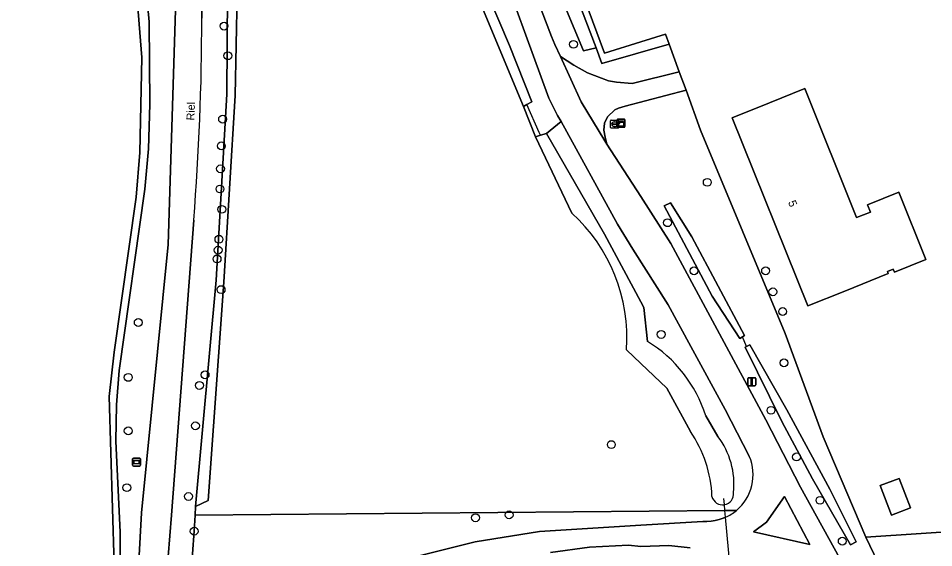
# Model space of a CAD drawing. Extents: x 163859 to 164644, y 379566 to 382155.
# Drawn here: x 164422.2 to 164536.6, y 381338.2 to 381404.3 of the extents above; entities that cross this region are included whole.
import ezdxf

# ---------------------------------------------------------------- set-up
doc = ezdxf.new("R2010")
doc.units = 0
for name, color, linetype in [('IMGEO_Boom', 7, 'Continuous'), ('IMGEO_Duiker', 7, 'Continuous'), ('IMGEO_Erf', 7, 'Continuous'), ('IMGEO_Grasland_agrarisch', 7, 'Continuous'), ('IMGEO_Grasland_overig', 7, 'Continuous'), ('IMGEO_Groenvoorziening', 7, 'Continuous'), ('IMGEO_Informatiebord', 7, 'Continuous'), ('IMGEO_Kast', 7, 'Continuous'), ('IMGEO_Lichtmast', 7, 'Continuous'), ('IMGEO_Openbare_ruimte_label', 7, 'Continuous'), ('IMGEO_Pand', 7, 'Continuous'), ('IMGEO_Pand_nummerreeks', 7, 'Continuous'), ('IMGEO_Rijbaan_lokaal_gesloten', 7, 'Continuous'), ('IMGEO_Rijbaan_lokaal_onverhard', 7, 'Continuous'), ('IMGEO_Rioolput', 7, 'Continuous'), ('IMGEO_Waterloop', 7, 'Continuous')]:
    doc.layers.add(name, color=color, linetype=linetype)

msp = doc.modelspace()

# ---------------------------------------------------------------- linework, layer by layer
at = {"layer": 'IMGEO_Boom'}
for centre in [(164447.92, 381403.31), (164491.58, 381401.04), (164448.4, 381399.61), (164447.74, 381391.69), (164447.58, 381388.35), (164447.48, 381385.49), (164447.41, 381382.97), (164508.3, 381383.8), (164447.64, 381380.42), (164503.34, 381378.75), (164447.28, 381376.69), (164447.18, 381375.33), (164447.05, 381374.23), (164506.65, 381372.74), (164515.59, 381372.75), (164447.55, 381370.4), (164516.5, 381370.12), (164517.72, 381367.66), (164437.2, 381366.29), (164502.54, 381364.8), (164517.89, 381361.25), (164435.95, 381359.43), (164445.55, 381359.75), (164444.85, 381358.43), (164516.26, 381355.32), (164444.35, 381353.39), (164435.95, 381352.75), (164496.32, 381351.04), (164519.46, 381349.5), (164435.78, 381345.66), (164443.48, 381344.56), (164522.39, 381344.08), (164479.34, 381341.9), (164483.54, 381342.26), (164444.19, 381340.22), (164525.17, 381338.97)]:
    msp.add_circle(centre, 0.489, dxfattribs=at)
at = {"layer": 'IMGEO_Duiker'}
for points in [[(164487.45, 381389.67), (164487.29, 381390.03), (164485.77, 381393.51)], [(164513.19, 381363.29), (164512.71, 381364.51)], [(164511.24, 381334.6), (164511.23, 381334.72), (164510.95, 381337.93), (164510.59, 381341.96), (164510.51, 381342.79), (164510.45, 381343.54), (164510.38, 381344.3)]]:
    msp.add_lwpolyline(points, dxfattribs=at)
at = {"layer": 'IMGEO_Erf'}
for points in [[(164565.06, 381406.39), (164564.53, 381407.1), (164559.87, 381421.34), (164557.52, 381431.13), (164500, 381418.46), (164489.46, 381416.14), (164495.45, 381399.95), (164500, 381401.35), (164503.1, 381402.3), (164503.54, 381401.07), (164504.8, 381397.62), (164505.66, 381395.29), (164507.47, 381390.32), (164518.04, 381364.93), (164522.77, 381352.02), (164528.1, 381339.46), (164564.56, 381341.91), (164578.44, 381343.7), (164575.05, 381361.38)], [(164535.63, 381374.14), (164531.69, 381372.56), (164531.54, 381372.95), (164530.81, 381372.66), (164530.92, 381372.39), (164525.51, 381370.22), (164520.86, 381368.36), (164511.43, 381391.87), (164516.07, 381393.74), (164520.5, 381395.51), (164526.97, 381379.39), (164528.68, 381380.07), (164528.32, 381380.98), (164532.25, 381382.56)], [(164533.68, 381343.13), (164531.33, 381342.22), (164529.9, 381345.91), (164532.26, 381346.82)]]:
    msp.add_lwpolyline(points, close=True, dxfattribs=at)
at = {"layer": 'IMGEO_Grasland_agrarisch'}
msp.add_lwpolyline([(164483.06, 381430.48), (164490.42, 381411.1), (164490.61, 381410.59), (164490.75, 381410.23), (164494.4, 381400.61), (164495.14, 381398.66), (164503.54, 381401.07), (164503.1, 381402.3), (164500, 381401.35), (164495.45, 381399.95), (164489.46, 381416.14), (164500, 381418.46), (164557.52, 381431.13), (164557.45, 381431.4), (164557.26, 381432.21), (164549, 381466.6), (164546.85, 381478.96), (164529.2, 381476.95), (164529.29, 381476.74), (164517.19, 381468.15), (164512.46, 381467.01), (164475.43, 381450.48), (164478.57, 381441.47)], dxfattribs=at)
at = {"layer": 'IMGEO_Grasland_overig'}
msp.add_lwpolyline([(164564.61, 381431.54), (164564.53, 381431.95), (164564.32, 381432.7), (164557.45, 381431.4), (164557.52, 381431.13), (164559.87, 381421.34), (164564.53, 381407.1), (164565.06, 381406.39), (164575.05, 381361.38), (164578.44, 381343.7), (164564.56, 381341.91), (164528.1, 381339.46), (164536.3, 381322.47), (164537.45, 381326.82), (164537.92, 381328.61), (164537.74, 381328.6)], dxfattribs=at)
at = {"layer": 'IMGEO_Groenvoorziening'}
for points in [[(164437.62, 381342.51), (164440.93, 381376.03), (164442.03, 381410.67), (164442.31, 381432.69), (164442.26, 381444.54), (164442.24, 381448.35), (164442.22, 381457.68), (164442.22, 381458.62), (164442.05, 381465.53), (164441.98, 381468.27), (164441.6, 381500), (164440.42, 381600.95)], [(164438.34, 381499.7), (164438.46, 381494.53), (164440.25, 381494.63), (164440.8, 381475.11), (164440.95, 381465.52), (164440.98, 381463.45), (164439.18, 381444.59), (164438.14, 381433.63), (164436.48, 381433.86), (164436.26, 381427.88), (164437.58, 381427.9), (164437.21, 381424.46), (164437.16, 381415.96), (164437.47, 381412.38), (164438.23, 381407.47), (164438.58, 381403.85), (164438.66, 381393.57), (164438.49, 381387.99), (164438.01, 381382.93), (164434.81, 381360.28), (164434.48, 381356.02), (164434.38, 381351.46), (164434.92, 381340.08), (164434.91, 381333.02)], [(164445.79, 381457.7), (164445.75, 381455.9), (164445.61, 381444.5), (164445.14, 381404.29)], [(164479.27, 381411.35), (164479.59, 381410.3), (164483.6, 381400.91), (164486.37, 381393.84), (164485.77, 381393.51), (164485.33, 381393.26), (164486.82, 381389.49), (164487.45, 381389.67), (164488.22, 381389.88), (164490.06, 381391.38), (164489.58, 381392.13), (164488.52, 381394.29), (164481.62, 381413.16), (164472.89, 381433.3), (164468.06, 381442.36), (164461.3, 381450.96), (164453.83, 381458.42)], [(164444.13, 381379.08), (164441.34, 381342.21), (164440.75, 381334.49), (164440.65, 381333.45), (164440.79, 381332.88), (164440.97, 381332.32), (164441.21, 381331.78), (164441.49, 381331.26), (164441.81, 381330.78), (164442.18, 381330.32), (164442.58, 381329.9), (164443.03, 381329.51), (164443.5, 381329.17), (164443.79, 381334.56), (164444.19, 381340.22), (164444.31, 381342.24), (164444.37, 381343.32), (164446.95, 381371.56), (164448.25, 381394.83), (164448.45, 381420.11), (164447.94, 381444.47), (164447.88, 381447.15), (164448.54, 381452.5)], [(164449.93, 381450.68), (164449.82, 381420.02), (164449.32, 381394.65), (164447.9, 381371.31), (164445.92, 381344.04), (164444.37, 381343.32), (164444.31, 381342.24), (164510.51, 381342.79), (164511.93, 381342.81)], [(164478.57, 381441.47), (164475.43, 381450.48), (164471, 381448.5), (164469.83, 381445.64), (164475.49, 381433.77), (164484.2, 381414.14), (164488.82, 381402.01), (164489.26, 381401.03), (164489.95, 381399.53), (164491.62, 381398.45), (164493.32, 381397.48), (164495.95, 381396.49), (164496.96, 381396.31), (164498.9, 381396.14), (164504.8, 381397.62), (164503.54, 381401.07), (164495.14, 381398.66), (164494.4, 381400.61), (164492.84, 381400.24), (164481.04, 381428.46)], [(164434.19, 381336.08), (164433.57, 381357.04), (164434.19, 381362.6), (164436.96, 381381.93), (164437.41, 381387.54), (164437.63, 381399.41), (164436.95, 381408.32), (164436.41, 381411.28), (164435.98, 381417.22), (164436.15, 381420.7), (164436.03, 381423.26), (164436.26, 381427.88), (164436.48, 381433.86), (164436.54, 381434.61), (164436.27, 381435.91), (164435.14, 381436.53), (164433.06, 381437.13), (164419.72, 381439.84)], [(164491.37, 381379.95), (164486.82, 381389.49), (164485.33, 381393.26), (164477.93, 381411.1)], [(164536.3, 381322.47), (164528.1, 381339.46), (164522.77, 381352.02), (164518.04, 381364.93), (164507.47, 381390.32), (164505.66, 381395.29), (164498.04, 381393.32), (164497.2, 381393.06), (164496.74, 381392.84), (164495.84, 381391.97), (164495.47, 381391.17), (164495.39, 381390.32), (164495.53, 381389.45), (164495.77, 381388.57), (164500, 381382.04), (164503.75, 381376.16), (164515.61, 381354.14), (164519.97, 381345.71), (164525.51, 381335.7)], [(164513.55, 381349.6), (164510.53, 381355.42), (164506.25, 381363.3), (164503.41, 381368.49), (164499.01, 381375.46), (164497.08, 381378.56), (164490.06, 381391.38), (164488.22, 381389.88), (164495.48, 381377.34), (164500, 381368.88), (164500.39, 381368.15), (164500.84, 381363.93)], [(164506.21, 381352.67), (164503.23, 381358.09), (164500, 381361.18), (164498.22, 381362.87)], [(164508.12, 381354.62), (164509.63, 381352.06)], [(164425.7, 381295.54), (164428.74, 381302.37), (164431.24, 381307.56), (164433.55, 381313.72), (164435.38, 381319.58), (164436.27, 381323.37), (164436.86, 381328.83), (164437.62, 381342.51)], [(164511.93, 381342.81), (164510.51, 381342.79), (164444.31, 381342.24), (164444.19, 381340.22), (164443.79, 381334.56), (164443.5, 381329.17), (164444.01, 381328.87), (164444.54, 381328.61), (164445.09, 381328.41), (164445.65, 381328.25), (164446.23, 381328.15), (164446.81, 381328.1), (164447.4, 381328.1), (164447.99, 381328.15), (164448.56, 381328.25), (164449.13, 381328.41), (164449.43, 381328.52), (164464.88, 381334.66)], [(164464.88, 381334.66), (164471.46, 381336.92), (164479.32, 381338.91), (164487.33, 381340.19), (164500, 381340.97), (164507.73, 381341.45), (164508.25, 381341.43), (164508.78, 381341.47), (164509.29, 381341.54), (164509.8, 381341.67), (164510.3, 381341.84), (164510.59, 381341.96)], [(164506.16, 381338.16), (164503.52, 381338.44), (164500, 381338.33), (164498.45, 381338.47), (164493.57, 381338.22), (164488.73, 381337.54)]]:
    msp.add_lwpolyline(points, dxfattribs=at)
for points in [[(164512.96, 381364.66), (164512.71, 381364.51), (164512.38, 381364.31), (164508.91, 381369.56), (164502.9, 381380.88), (164503.7, 381381.24), (164506.38, 381376.97)], [(164518.23, 381355.39), (164523.62, 381345.49), (164526.91, 381338.9), (164526.21, 381338.53), (164521.46, 381346.77), (164517.64, 381353.91), (164513.02, 381363.21), (164513.19, 381363.29), (164513.62, 381363.49)], [(164521.12, 381338.58), (164517.97, 381344.54), (164515.72, 381341.34), (164514.08, 381340.16)]]:
    msp.add_lwpolyline(points, close=True, dxfattribs=at)
for centre, radius, start, end in [((164127.19, 381404.33), 317.95, 355.4455, 359.9916), ((164477.32, 381364.4), 20.95, 355.8205, 47.8876), ((164491.98, 381349.5), 16.93, 17.6325, 58.4553), ((164493.52, 381343.98), 15.38, 2.1274, 34.4033), ((164501.78, 381346.09), 9.86, 353.957, 37.2698), ((164508.17, 381347.29), 5.86, 310.0111, 23.194), ((164510.22, 381344.89), 1.38, 194.5224, 279.6002), ((164510.22, 381344.9), 1.38, 279.6512, 6.4516), ((164508.16, 381347.3), 5.87, 294.4431, 310.0184)]:
    msp.add_arc(centre, radius, start, end, dxfattribs=at)
at = {"layer": 'IMGEO_Informatiebord'}
for p, q in [((164436.49, 381348.45), (164436.49, 381349.25)), ((164436.49, 381349.25), (164436.49, 381348.45)), ((164436.59, 381349.35), (164437.38, 381349.35)), ((164437.38, 381349.35), (164436.59, 381349.35)), ((164437.48, 381349.25), (164437.48, 381348.45)), ((164437.48, 381348.45), (164437.48, 381349.25)), ((164437.38, 381348.35), (164436.59, 381348.35)), ((164436.59, 381348.35), (164437.38, 381348.35))]:
    msp.add_line(p, q, dxfattribs=at)
for points in [[(164436.6, 381349.08), (164437.38, 381349.08), (164437.38, 381348.62), (164436.6, 381348.62), (164436.6, 381349.08)], [(164436.66, 381349.02), (164436.66, 381348.68), (164437.32, 381348.68), (164437.32, 381349.02), (164436.66, 381349.02)]]:
    msp.add_lwpolyline(points, dxfattribs=at)
for centre, start, end in [((164436.59, 381349.25), 90, 180), ((164436.59, 381349.25), 90, 180), ((164437.38, 381349.25), 0, 90), ((164437.38, 381349.25), 360, 90), ((164436.59, 381348.45), 180, 270), ((164436.59, 381348.45), 180, 270), ((164437.38, 381348.45), 270, 0), ((164437.38, 381348.45), 270, 0)]:
    msp.add_arc(centre, 0.1, start, end, dxfattribs=at)
at = {"layer": 'IMGEO_Kast'}
for p, q in [((164497.02, 381390.76), (164497.02, 381391.6)), ((164497.02, 381391.6), (164497.02, 381390.76)), ((164497.1, 381391.68), (164497.94, 381391.68)), ((164497.94, 381391.68), (164497.1, 381391.68)), ((164498.02, 381391.61), (164498.02, 381390.77)), ((164498.02, 381390.77), (164498.02, 381391.61)), ((164497.95, 381390.68), (164497.11, 381390.68)), ((164497.11, 381390.68), (164497.95, 381390.68))]:
    msp.add_line(p, q, dxfattribs=at)
for points in [[(164497.22, 381391.47), (164497.82, 381391.47), (164497.82, 381391.39), (164497.22, 381391.39), (164497.22, 381391.47)], [(164497.22, 381391.3), (164497.82, 381391.3), (164497.82, 381390.81), (164497.22, 381390.81), (164497.22, 381391.3)]]:
    msp.add_lwpolyline(points, dxfattribs=at)
msp.add_circle((164497.3, 381391.14), 0.0377, dxfattribs=at)
for centre, start, end in [((164497.1, 381391.6), 92.4484, 184.2845), ((164497.1, 381391.6), 92.4484, 184.2845), ((164497.94, 381391.6), 2.4484, 94.2845), ((164497.94, 381391.6), 2.4484, 94.2845), ((164497.1, 381390.76), 182.4484, 274.2845), ((164497.1, 381390.76), 182.4484, 274.2845), ((164497.94, 381390.76), 272.4484, 4.2845), ((164497.94, 381390.76), 272.4484, 4.2845)]:
    msp.add_arc(centre, 0.0779, start, end, dxfattribs=at)
at = {"layer": 'IMGEO_Lichtmast'}
for p, q in [((164513.37, 381358.49), (164513.37, 381359.29)), ((164513.37, 381359.29), (164513.37, 381358.49)), ((164513.47, 381359.39), (164514.25, 381359.39)), ((164514.25, 381359.39), (164513.47, 381359.39)), ((164514.35, 381359.29), (164514.35, 381358.49)), ((164514.35, 381358.49), (164514.35, 381359.29)), ((164514.25, 381358.39), (164513.47, 381358.39)), ((164513.47, 381358.39), (164514.25, 381358.39))]:
    msp.add_line(p, q, dxfattribs=at)
msp.add_lwpolyline([(164513.78, 381359.26), (164513.93, 381359.26), (164513.93, 381358.51), (164513.78, 381358.51), (164513.78, 381359.26)], dxfattribs=at)
for centre, start, end in [((164513.47, 381359.29), 90, 180), ((164513.47, 381359.29), 90, 180), ((164514.25, 381359.29), 0, 90), ((164514.25, 381359.29), 360, 90), ((164513.47, 381358.49), 180, 270), ((164513.47, 381358.49), 180, 270), ((164514.25, 381358.49), 270, 0), ((164514.25, 381358.49), 270, 0)]:
    msp.add_arc(centre, 0.1, start, end, dxfattribs=at)
at = {"layer": 'IMGEO_Pand'}
for points in [[(164520.5, 381395.51), (164516.07, 381393.74), (164511.43, 381391.87), (164520.86, 381368.36), (164525.51, 381370.22), (164530.92, 381372.39), (164530.81, 381372.66), (164531.54, 381372.95), (164531.69, 381372.56), (164535.63, 381374.14), (164532.25, 381382.56), (164528.32, 381380.98), (164528.68, 381380.07), (164526.97, 381379.39)], [(164531.33, 381342.22), (164533.68, 381343.13), (164532.26, 381346.82), (164529.9, 381345.91)]]:
    msp.add_lwpolyline(points, close=True, dxfattribs=at)
at = {"layer": 'IMGEO_Rijbaan_lokaal_gesloten'}
for points in [[(164445.14, 381404.29), (164445.61, 381444.5), (164445.75, 381455.9), (164445.79, 381457.7), (164442.22, 381457.68), (164442.24, 381448.35), (164442.26, 381444.54), (164442.31, 381432.69), (164442.03, 381410.67), (164440.93, 381376.03), (164437.62, 381342.51), (164436.86, 381328.83), (164436.27, 381323.37), (164435.38, 381319.58), (164433.55, 381313.72), (164431.24, 381307.56), (164428.74, 381302.37), (164431.96, 381299.66)], [(164438.88, 381318.31), (164439.5, 381323.04), (164440.12, 381327.77), (164440.15, 381328.05), (164440.65, 381333.45), (164440.75, 381334.49), (164441.34, 381342.21), (164444.13, 381379.08)]]:
    msp.add_lwpolyline(points, dxfattribs=at)
msp.add_arc((164127.19, 381404.33), 317.95, 355.4455, 359.9916, dxfattribs=at)
at = {"layer": 'IMGEO_Rijbaan_lokaal_onverhard'}
for points in [[(164519.97, 381345.71), (164515.61, 381354.14), (164503.75, 381376.16), (164500, 381382.04), (164495.77, 381388.57), (164495.51, 381388.98), (164492.54, 381393.86), (164489.95, 381399.53), (164489.26, 381401.03), (164488.82, 381402.01), (164484.2, 381414.14)], [(164481.62, 381413.16), (164488.52, 381394.29), (164489.58, 381392.13), (164490.06, 381391.38), (164497.08, 381378.56), (164499.01, 381375.46), (164503.41, 381368.49), (164506.25, 381363.3), (164510.53, 381355.42), (164513.55, 381349.6)], [(164538.24, 381280.07), (164536.24, 381278.12), (164544.02, 381275.23), (164542.93, 381279.72), (164542, 381286.69), (164541.11, 381291.26), (164540.2, 381293.84), (164532.72, 381318.95), (164531.51, 381322.61), (164529.04, 381328.58), (164527.86, 381330.74), (164525.51, 381335.7), (164519.97, 381345.71)], [(164510.59, 381341.96), (164510.3, 381341.84), (164509.8, 381341.67), (164509.29, 381341.54), (164508.78, 381341.47), (164508.25, 381341.43), (164507.73, 381341.45), (164500, 381340.97), (164487.33, 381340.19), (164479.32, 381338.91), (164471.46, 381336.92)], [(164488.73, 381337.54), (164493.57, 381338.22), (164498.45, 381338.47), (164500, 381338.33), (164503.52, 381338.44), (164506.16, 381338.16)]]:
    msp.add_lwpolyline(points, dxfattribs=at)
for points in [[(164505.66, 381395.29), (164504.8, 381397.62), (164498.9, 381396.14), (164496.96, 381396.31), (164495.95, 381396.49), (164493.32, 381397.48), (164491.62, 381398.45), (164489.95, 381399.53), (164492.54, 381393.86), (164495.51, 381388.98), (164495.77, 381388.57), (164495.53, 381389.45), (164495.39, 381390.32), (164495.47, 381391.17), (164495.84, 381391.97), (164496.74, 381392.84), (164497.2, 381393.06), (164498.04, 381393.32)], [(164517.97, 381344.54), (164521.12, 381338.58), (164514.08, 381340.16), (164515.72, 381341.34)]]:
    msp.add_lwpolyline(points, close=True, dxfattribs=at)
for centre, radius, start, end in [((164508.17, 381347.29), 5.86, 310.0111, 23.194), ((164508.16, 381347.3), 5.87, 294.4431, 310.0184)]:
    msp.add_arc(centre, radius, start, end, dxfattribs=at)
at = {"layer": 'IMGEO_Rioolput'}
for p, q in [((164496.23, 381390.64), (164496.23, 381391.49)), ((164496.3, 381391.56), (164497.16, 381391.56)), ((164496.72, 381391.34), (164496.74, 381391.34)), ((164497.23, 381391.49), (164497.23, 381390.64)), ((164497.16, 381390.56), (164496.3, 381390.56)), ((164496.49, 381391.06), (164496.49, 381391.07)), ((164496.53, 381391.11), (164496.93, 381391.11)), ((164496.92, 381391.02), (164496.53, 381391.02)), ((164496.74, 381390.78), (164496.71, 381390.78)), ((164496.97, 381391.07), (164496.97, 381391.06))]:
    msp.add_line(p, q, dxfattribs=at)
for points in [[(164496.23, 381390.64), (164496.23, 381391.49)], [(164496.3, 381391.56), (164497.16, 381391.56)], [(164497.23, 381391.49), (164497.23, 381390.64)], [(164497.16, 381390.56), (164496.3, 381390.56)]]:
    msp.add_lwpolyline(points, dxfattribs=at)
for centre, radius, start, end in [((164496.3, 381391.49), 0.0765, 91.552, 178.448), ((164496.3, 381391.49), 0.0765, 91.552, 178.448), ((164497.15, 381391.49), 0.0765, 1.552, 88.448), ((164497.15, 381391.49), 0.0765, 1.552, 88.448), ((164496.3, 381390.64), 0.0765, 181.552, 268.448), ((164496.3, 381390.64), 0.0765, 181.552, 268.448), ((164496.53, 381391.07), 0.0403, 85.8775, 175.7526), ((164496.52, 381391.06), 0.0366, 178.938, 274.7102), ((164496.93, 381391.06), 0.043, 264.8664, 352.4533), ((164496.93, 381391.07), 0.0386, 1.7309, 96.639), ((164497.15, 381390.64), 0.0765, 271.552, 358.448), ((164497.15, 381390.64), 0.0765, 271.552, 358.448)]:
    msp.add_arc(centre, radius, start, end, dxfattribs=at)
for centre, major_axis, ratio, start_param, end_param in [((164496.72, 381391.06), (-0.387, 0.002), 0.722429, 4.712389, 7.853982), ((164496.74, 381391.06), (-0.39, 0.002), 0.717154, 1.570796, 4.712389)]:
    msp.add_ellipse(centre, major_axis=major_axis, ratio=ratio, start_param=start_param, end_param=end_param, dxfattribs=at)
at = {"layer": 'IMGEO_Waterloop'}
for points in [[(164448.54, 381452.5), (164447.88, 381447.15), (164447.94, 381444.47), (164448.45, 381420.11), (164448.25, 381394.83), (164446.95, 381371.56), (164444.37, 381343.32), (164445.92, 381344.04), (164447.9, 381371.31), (164449.32, 381394.65), (164449.82, 381420.02), (164449.93, 381450.68)], [(164476.7, 381445.19), (164475.23, 381443.5), (164481.04, 381428.46), (164492.84, 381400.24), (164494.4, 381400.61), (164490.75, 381410.23), (164490.61, 381410.59), (164490.42, 381411.1), (164483.06, 381430.48)], [(164472.47, 381424.73), (164477.93, 381411.1), (164485.33, 381393.26), (164485.77, 381393.51), (164486.37, 381393.84), (164483.6, 381400.91), (164479.59, 381410.3), (164479.27, 381411.35)], [(164436.95, 381408.32), (164437.63, 381399.41), (164437.41, 381387.54), (164436.96, 381381.93), (164434.19, 381362.6), (164433.57, 381357.04), (164434.19, 381336.08)], [(164434.91, 381333.02), (164434.92, 381340.08), (164434.38, 381351.46), (164434.48, 381356.02), (164434.81, 381360.28), (164438.01, 381382.93), (164438.49, 381387.99), (164438.66, 381393.57), (164438.58, 381403.85), (164438.23, 381407.47)], [(164500.84, 381363.93), (164500.39, 381368.15), (164500, 381368.88), (164495.48, 381377.34), (164488.22, 381389.88), (164487.45, 381389.67), (164486.82, 381389.49), (164491.37, 381379.95)], [(164498.22, 381362.87), (164500, 381361.18), (164503.23, 381358.09), (164506.21, 381352.67)], [(164509.63, 381352.06), (164508.12, 381354.62)]]:
    msp.add_lwpolyline(points, dxfattribs=at)
for points in [[(164512.71, 381364.51), (164512.96, 381364.66), (164506.38, 381376.97), (164503.7, 381381.24), (164502.9, 381380.88), (164508.91, 381369.56), (164512.38, 381364.31)], [(164513.19, 381363.29), (164513.02, 381363.21), (164517.64, 381353.91), (164521.46, 381346.77), (164526.21, 381338.53), (164526.91, 381338.9), (164523.62, 381345.49), (164518.23, 381355.39), (164513.62, 381363.49)]]:
    msp.add_lwpolyline(points, close=True, dxfattribs=at)
for centre, radius, start, end in [((164477.32, 381364.4), 20.95, 355.8205, 47.8876), ((164491.98, 381349.5), 16.93, 17.6325, 58.4553), ((164493.52, 381343.98), 15.38, 2.1274, 34.4033), ((164501.78, 381346.09), 9.86, 353.957, 37.2698), ((164510.22, 381344.89), 1.38, 194.5224, 279.6002), ((164510.22, 381344.9), 1.38, 279.6512, 6.4516)]:
    msp.add_arc(centre, radius, start, end, dxfattribs=at)

# ---------------------------------------------------------------- texts
at = {"layer": 'IMGEO_Openbare_ruimte_label'}
msp.add_text('Riel', height=1, rotation=88.3389, dxfattribs=at).set_placement((164444.22, 381391.52))
at = {"layer": 'IMGEO_Pand_nummerreeks'}
msp.add_text('5', height=1, rotation=291.8639, dxfattribs=at).set_placement((164518.38, 381381.31))

doc.saveas('drawing.dxf')
